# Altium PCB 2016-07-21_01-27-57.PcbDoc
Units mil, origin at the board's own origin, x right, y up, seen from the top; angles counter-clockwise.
Board outline 3150 x 2500 mil, 4 copper layers (Top Layer, MidLayer1, MidLayer2, Bottom Layer); 21 components, 13 nets, 50 pads, 42 vias.
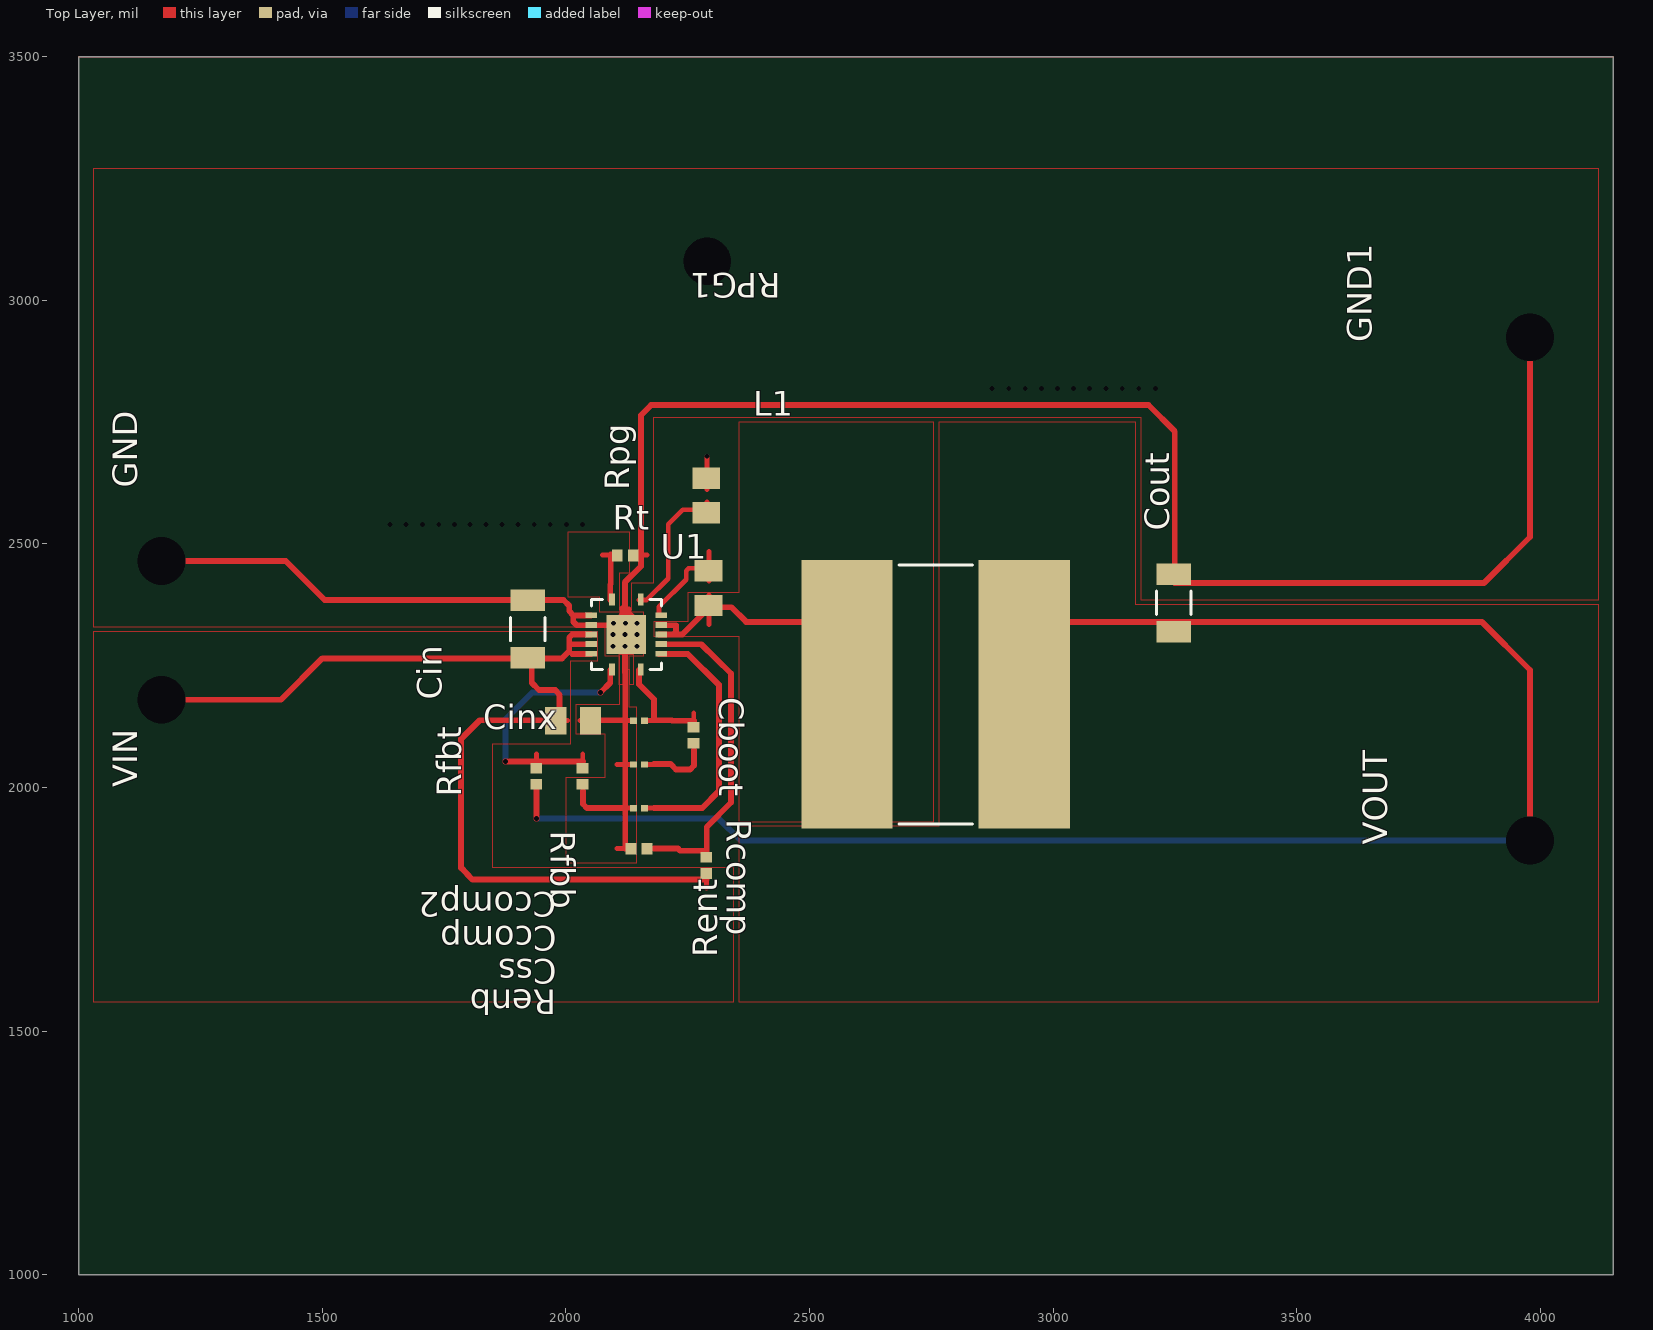
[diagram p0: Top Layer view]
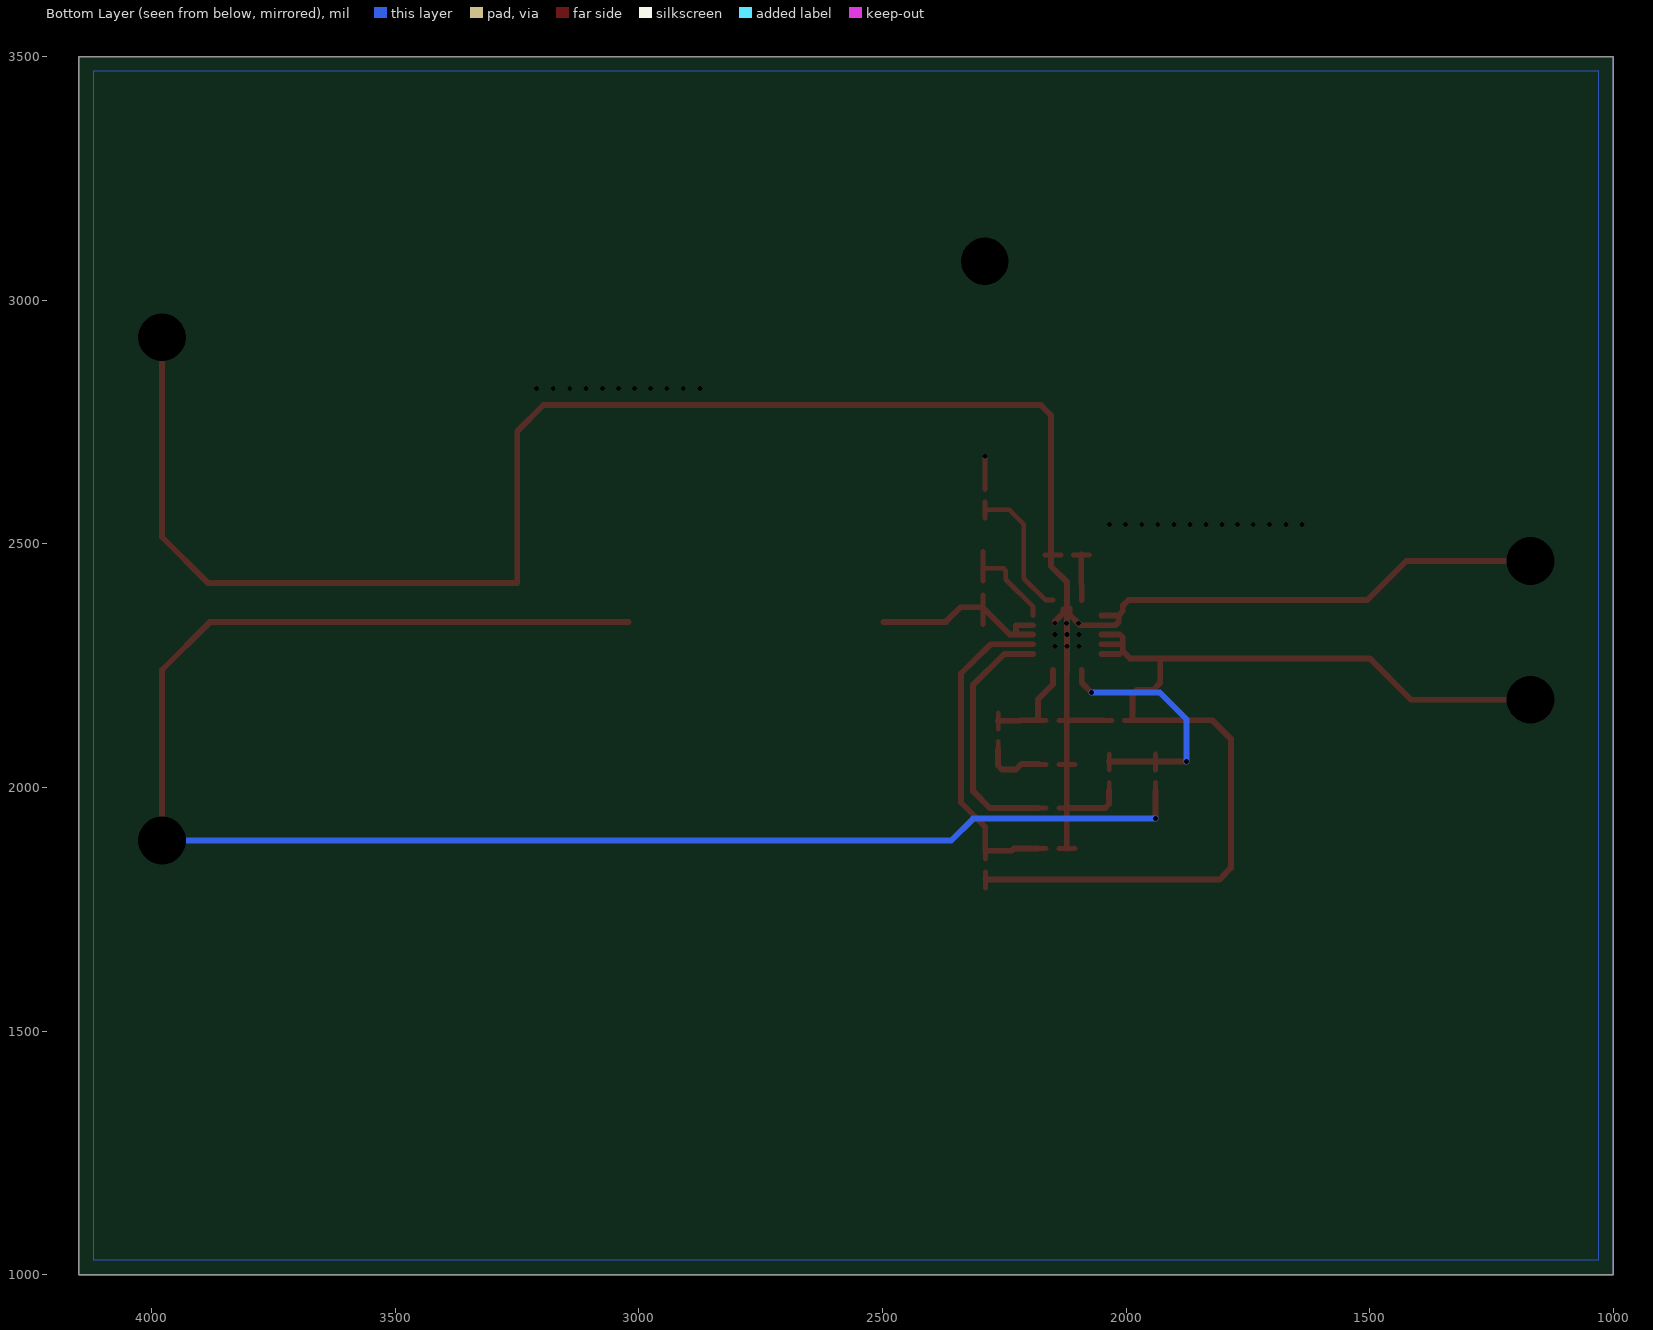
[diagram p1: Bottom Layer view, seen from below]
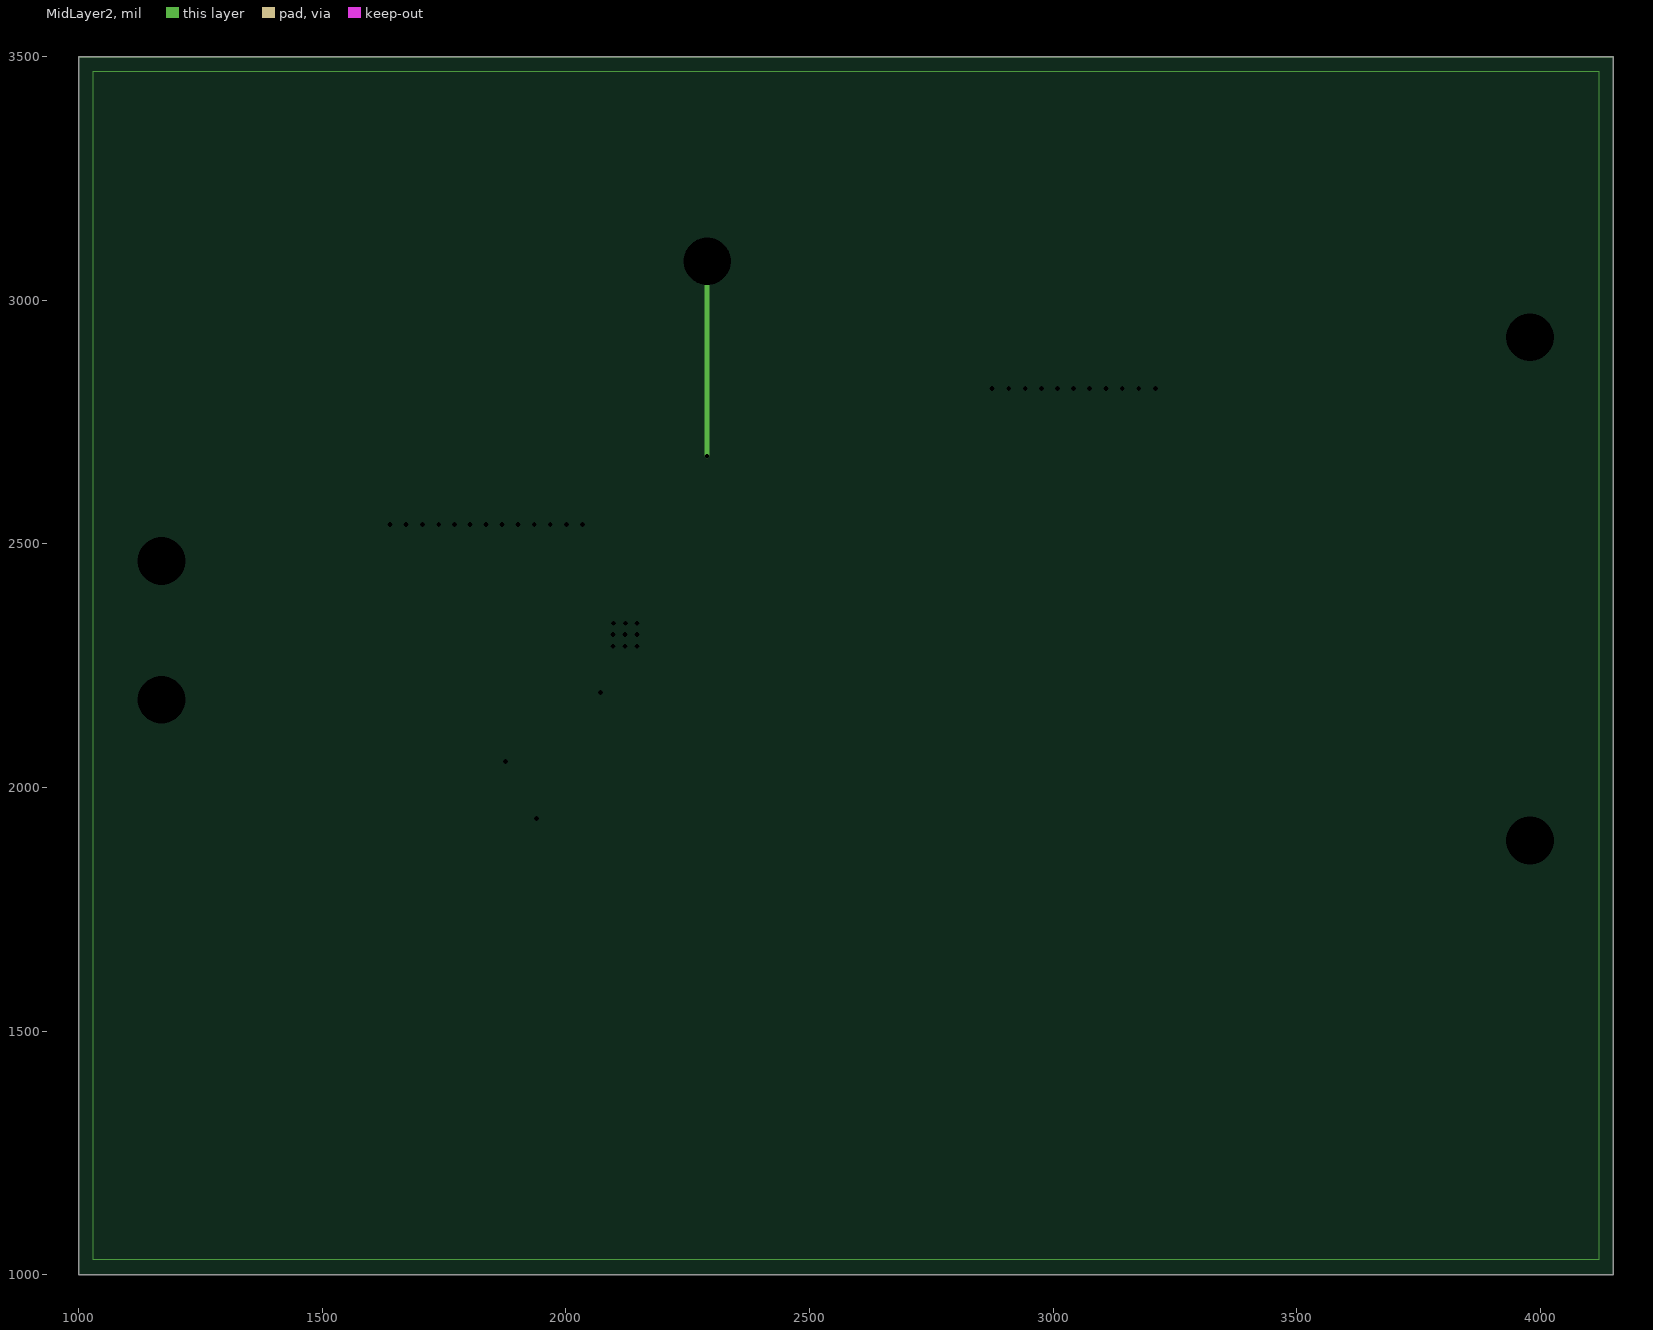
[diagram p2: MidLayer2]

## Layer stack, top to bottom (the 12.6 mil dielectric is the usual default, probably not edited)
Top Layer: signal copper 1.4
Dielectric: core 12.6, FR-4, Dk 4.8
MidLayer1: signal copper 1.4
Dielectric: prepreg 12.6, FR-4, Dk 4.8
MidLayer2: signal copper 1.4
Dielectric: core 12.6, FR-4, Dk 4.8
Bottom Layer: signal copper 1.4

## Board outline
1000,1000 4150,1000 4150,3500 1000,3500

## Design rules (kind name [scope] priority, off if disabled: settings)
PlaneConnect [All] p0: scope1count=1 scope1_0_kind=Board scope1_0_value=Board scope2count=1 scope2_0_kind=Board scope2_0_value=Board commentlength=0 planeconnectstyle=Direct reliefexpansion=20 reliefentries=4 reliefconductorwidth=10 reliefairgap=10
PlaneConnect [All] p1: planeconnectstyle=Direct reliefexpansion=20 reliefentries=4 reliefconductorwidth=10 reliefairgap=10
PolygonConnect [All] p0: scope1count=1 scope1_0_kind=Board scope1_0_value=Board scope2count=1 scope2_0_kind=Board scope2_0_value=Board commentlength=0 connectstyle=Direct reliefconductorwidth=10 reliefentries=4 polygonreliefangle="90 Angle"
PolygonConnect [All] p1: connectstyle=Direct reliefconductorwidth=10 reliefentries=4 polygonreliefangle="90 Angle"

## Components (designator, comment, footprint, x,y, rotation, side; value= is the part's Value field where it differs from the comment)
Cboot "" 0805 2293,2409 r270 top
Ccomp "" 0201 2150,2047 r180 top
Ccomp2 "" 0201 2150,2137 r180 top
Cin "" 1206_190 1922,2325 r90 top
Cinx "" 0805 2015,2137 r0 top
Cout "" 1206_190 3248,2379 r90 top
Css "" 0201 2150,1957 r180 top
GND "" TP-1502 1168,2464 r90 top
GND1 "" TP-1502 3978,2923 r90 top
L1 "" SDR1307 2759,2191 r0 top
Rcomp "" 0402 2262,2107 r270 top
Renb "" 0402 2150,1874 r180 top
Rent "" 0402 2288,1840 r90 top
Rfbb "" 0402 2034,2023 r270 top
Rfbt "" 0402 1939,2023 r90 top
Rpg "" 0805 2288,2599 r90 top
RPG1 "" TP-1502 2288,3078 r180 top
Rt "" 0402 2122,2476 r0 top
U1 "" S-PVQFN-N14 2124,2314 r0 top
VIN "" TP-1502 1168,2179 r90 top
VOUT "" TP-1502 3978,1890 r90 top

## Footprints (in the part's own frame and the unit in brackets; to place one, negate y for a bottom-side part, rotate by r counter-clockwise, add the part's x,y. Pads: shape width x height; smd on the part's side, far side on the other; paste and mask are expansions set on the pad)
0201 [mil]
  rect 14x13 smd: 1(-11.5,0) 2(11.5,0)
0402 [mil]
  rect 22x24 smd: 1(-16.5,0) 2(16.5,0)
0805 [mil]
  rect 44x57 smd: 1(-35.5,0) 2(35.5,0)
1206_190 [mil]
  rect 44x71 smd: 1(-59,0) 2(59,0)
  silkscreen extent -24,-36 24,36
S-PVQFN-N14 [mil]
  rect 12x24 smd: 1(-29.53,71.85) 7(-29.53,-71.85) 8(29.53,-71.85) 14(29.53,71.85)
  rect 24x12 smd: 2(-71.85,39.37) 3(-71.85,19.68) 4(-71.85,0) 5(-71.85,-19.68) 6(-71.85,-39.37) 9(71.85,-39.37) 10(71.85,-19.68) 11(71.85,0) 12(71.85,19.68) 13(71.85,39.37)
  rect 80.71x80.71 smd: 15(0,0)
  silkscreen extent -72,-72 72,72
SDR1307 [mil]
  rect 187x551 smd: 1(-182,0) 2(182,0)
  silkscreen extent -75,-266 75,266
TP-1502 [mil]
  round 65 / inner round 0 / far side round 65 hole 32: 1(0,0)

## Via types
v1: diameter 0, hole 10, Top Layer to Bottom Layer, 37 vias
v2: diameter 0, hole 98, Top Layer to Bottom Layer, 5 vias

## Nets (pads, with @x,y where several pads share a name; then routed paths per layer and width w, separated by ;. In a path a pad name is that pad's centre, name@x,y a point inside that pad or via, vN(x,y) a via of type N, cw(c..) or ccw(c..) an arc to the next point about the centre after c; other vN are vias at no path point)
0: Ccomp2.2 Ccomp.2 Cin.2 Cinx.2 Cout.2 Css.2 GND1.1 GND.1 Renb.2 Rfbb.2 Rt.2 U1.2 U1.3 U1.15 | length 5053.8
  Top Layer w10: Cinx.2@2029,2137.5 Cinx.2@2062,2137.5 ; 2034.5,1977 Rfbb.2@2034.5,2010 ; 2105,1874.5 Renb.2@2138,1874.5 ; 2105,1957.5 Css.2@2138,1957.5 ; 2105,2047.5 Ccomp.2@2138,2047.5 ; 2105,2137.5 Ccomp2.2@2138,2137.5 ; U1.15@2115,2353 2115,2369 ; Rt.2@2134,2477.5 2167,2477.5
  Top Layer w12: v2(1170,2465) 1425,2465 1505,2385 1930,2385 1995,2385 2007,2373 2007,2362 2015,2353 ; 2035,1994 2035,1966 2043,1958 2122,1958 ; Cinx.2@2046,2138 2122,2138 ; U1.2@2051,2353 2015,2353 ; U1.15@2115,2353 2114,2353 v1(2098,2337) 2094,2333 2051,2333 2022,2333 2015,2340 2015,2353 ; 2122,1875 2122,1958 ; 2129,2365 2129,2358 2146,2341 v1(2146,2337) ; v2(3979,2924) 3979,2514 3885,2420 3250,2420 3250,2731 3196,2785 2175,2785 2154,2764 2154,2454 2121,2421 v1(2121,2314) 2121,2236 2122,2235 2122,2138 ; 2122,1958 2122,2048 2122,2138
  other v1: 2097,2290 2121,2290 2146,2290 2097,2314 2146,2314 2122,2337 1639,2540 1672,2540 1706,2540 1739,2540 1771,2540 1803,2540 1836,2540 1869,2540 1902,2540 1935,2540 1968,2540 2001,2540 2034,2540 2875,2819 2909,2819 2943,2819 2976,2819 3009,2819 3042,2819 3075,2819 3109,2819 3142,2819 3176,2819 3210,2819
1: Ccomp2.1 Rcomp.1 U1.8 | length 264.8
  Top Layer w10: Ccomp2.1@2164,2137.5 2197,2137.5 ; Rcomp.1@2262.5,2120 2262.5,2153
  Top Layer w12: U1.8@2150,2241 2150,2212 2181,2181 2181,2138 2218,2138 2218,2137 2263,2137
2: Renb.1 Rent.2 U1.10 | length 733.7
  Top Layer w10: Renb.1@2164,1874.5 2197,1874.5 ; Rent.2@2288.5,1853 2288.5,1886
  Top Layer w12: 2181,1875 2230,1875 2234,1870 2289,1870 2289,1919 2339,1969 2339,2234 2278,2294 U1.10@2191,2294
3: Rt.1 U1.1 | length 126.4
  Top Layer w10: 2075,2477.5 Rt.1@2108,2477.5
  Top Layer w12: U1.1@2091,2385 2091,2417 2092,2418 2092,2478
4: Css.1 U1.9 | length 547.9
  Top Layer w10: Css.1@2164,1957.5 2197,1957.5
  Top Layer w12: 2181,1958 2280,1958 2314,1992 2314,2211 2250,2274 U1.9@2191,2274
5: Cboot.2 L1.1 U1.11 U1.12 | length 460.1
  Top Layer w10: 2294,2334 Cboot.2@2294,2395
  Top Layer w12: U1.11@2191,2314 2220,2314 ; U1.12@2191,2333 2226,2333 2226,2320 2220,2314 ; L1.1@2498,2340 2370,2340 2340,2370 2295,2370 2239,2314 2220,2314
6: Rfbb.1 Rfbt.2 U1.7 | length 584.1
  Top Layer w10: Rfbt.2@1939.5,2036 1939.5,2069 ; Rfbb.1@2034.5,2036 2034.5,2069
  Top Layer w12: v1(1876,2053) 1940,2053 2035,2053 ; v1(2071,2195) 2091,2215 U1.7@2091,2241
  Bottom Layer w12: v1(1876,2053) 1876,2140 1931,2195 v1(2071,2195)
7: Cout.1 L1.2 Rfbt.1 VOUT.1 | length 3497.6
  Top Layer w10: 1939.5,1977 Rfbt.1@1939.5,2010
  Top Layer w12: v1(1940,1936) 1940,1994 ; L1.2@3021,2340 3250,2340 3880,2340 3979,2241 v2(3979,1891)
  Bottom Layer w12: v1(1940,1936) 2314,1936 2359,1891 v2(3979,1891)
8: Cin.1 Cinx.1 Rent.1 U1.4 U1.5 U1.6 VIN.1 | length 2267.6
  Top Layer w10: Cinx.1@1970,2137.5 2003,2137.5 ; 2288.5,1794 Rent.1@2288.5,1827
  Top Layer w12: v2(1170,2180) 1415,2180 1500,2265 Cin.1@1930,2265 ; 2013,2274 U1.6@2051,2274 ; U1.5@2051,2294 2007,2294 ; U1.4@2051,2314 2013,2314 2007,2308 2007,2294 ; 2289,1811 1808,1811 1785,1835 1785,2100 1823,2138 1987,2138 1987,2190 1978,2200 1945,2200 1930,2215 Cin.1@1930,2265 ; Cin.1@1930,2265 1992,2265 2007,2280 2007,2294
9: Ccomp.1 Rcomp.2 | length 188.9
  Top Layer w10: Ccomp.1@2164,2047.5 2197,2047.5 ; 2262.5,2061 Rcomp.2@2262.5,2094
  Top Layer w12: 2181,2048 2215,2048 2226,2037 2255,2037 2263,2045 2263,2078
10: Cboot.1 U1.13 | length 226.3
  Top Layer w10: U1.13@2191,2353 2191,2371 2247,2427 2247,2445 2252,2450 Cboot.1@2295,2450 ; Cboot.1@2294,2424 2294,2485
21: Rpg.1 U1.14 | length 314.7
  Top Layer w10: U1.14@2150,2385 2166,2385 2210,2429 2210,2540 2240,2570 Rpg.1@2290,2570 ; Rpg.1@2289.5,2553 2289.5,2586
23: RPG1.1 Rpg.2 | length 484
  Top Layer w10: 2289.5,2612 Rpg.2@2289.5,2645 ; Rpg.2@2290,2629 v1(2290,2680)
  MidLayer2 w10: v1(2290,2680) v2(2290,3080)

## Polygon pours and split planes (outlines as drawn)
7 on Top Layer " " (solid, pour order 0): 2355,1560 4120,1560 4120,2375 3170,2375 3170,2750 2765,2750 2765,1920 2355,1920
8 on Top Layer " " (solid, pour order 1): 2065,2320 1030,2320 1030,1560 2345,1560 2345,1835 1850,1835 1850,2090 2010,2090 2010,2260 2065,2260
5 on Top Layer " " (solid, pour order 2): 2180,2310 2355,2310 2355,1930 2755,1930 2755,2750 2355,2750 2355,2400 2250,2400 2250,2340 2180,2340
0 on Top Layer " " (solid, pour order 3): 3180,2760 3180,2385 4120,2385 4120,3270 1030,3270 1030,2330 2080,2330 2080,2270 2110,2270 2110,2170 2020,2170 2020,2110 2080,2110 2080,2020 2000,2020 2000,1845 2145,1845 2145,2165 2130,2165 2130,2270 2160,2270 2160,2360 2070,2360 2070,2390 2005,2390 2005,2525 2130,2525 2130,2440 2110,2440 2110,2365 2135,2365 2135,2420 2180,2420 2180,2760
0 on Bottom Layer " " (solid, pour order 6): 1030,1030 1030,3470 4120,3470 4120,1030
0 on MidLayer1 " " (solid, pour order 4): 1030,1030 1030,3470 4120,3470 4120,1030
0 on MidLayer2 " " (solid, pour order 5): 1030,1030 1030,3470 4120,3470 4120,1030
no net on Top Layer "Top Layer-No Net" (solid, remove dead copper): 2138.76,2273.65 2138.76,2210.65 2130.89,2210.65 2130.89,2242.15 2117.11,2242.15 2117.11,2210.65 2109.24,2210.65 2109.24,2273.65
no net on Top Solder "Top Layer-No Net" (solid, remove dead copper): 2138.76,2273.65 2138.76,2210.65 2130.89,2210.65 2130.89,2242.15 2117.11,2242.15 2117.11,2210.65 2109.24,2210.65 2109.24,2273.65
no net on Top Paste "Top Layer-No Net" (solid, remove dead copper): 2138.76,2273.65 2138.76,2210.65 2130.89,2210.65 2130.89,2273.65
no net on Top Paste "Top Layer-No Net" (solid, remove dead copper): 2117.11,2273.65 2117.11,2210.65 2109.24,2210.65 2109.24,2273.65

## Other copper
Multi-Layer:
  the board outline again, w1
